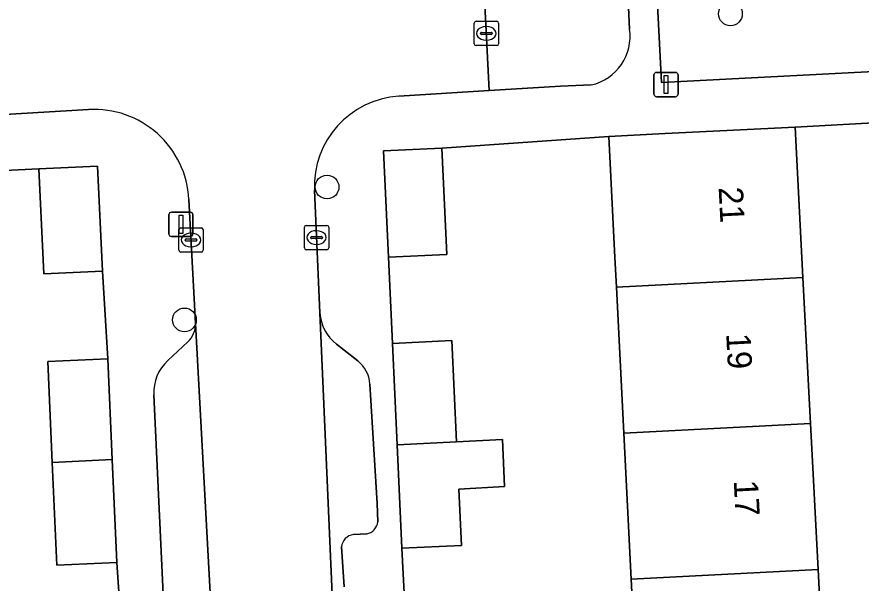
# Model space of a CAD drawing. Extents: x 161084 to 161928, y 385354 to 386522.
# Drawn here: x 161389.16 to 161423.93, y 385507.46 to 385530.8 of the extents above; entities that cross this region are included whole.
import ezdxf

# ---------------------------------------------------------------- set-up
doc = ezdxf.new("R2010")
doc.units = 0
for name, color, linetype in [('IMGEO_Boom', 7, 'Continuous'), ('IMGEO_Erf', 7, 'Continuous'), ('IMGEO_Groenvoorziening', 7, 'Continuous'), ('IMGEO_Kolk', 7, 'Continuous'), ('IMGEO_Lichtmast', 7, 'Continuous'), ('IMGEO_Muur', 7, 'Continuous'), ('IMGEO_Pand', 7, 'Continuous'), ('IMGEO_Pand_nummerreeks', 7, 'Continuous'), ('IMGEO_Parkeervlak_open', 7, 'Continuous'), ('IMGEO_Rijbaan_lokaal_open', 7, 'Continuous'), ('IMGEO_Voetpad_open', 7, 'Continuous')]:
    doc.layers.add(name, color=color, linetype=linetype)

msp = doc.modelspace()

# ---------------------------------------------------------------- linework, layer by layer
at = {"layer": 'IMGEO_Boom'}
for centre in [(161418.548, 385530.919), (161401.934, 385523.786), (161396.06, 385518.31)]:
    msp.add_circle(centre, 0.489, dxfattribs=at)
at = {"layer": 'IMGEO_Erf'}
for points in [[(161425.182, 385526.476), (161421.216, 385526.254), (161421.535, 385520.062), (161421.846, 385514.041), (161422.156, 385508.02), (161422.467, 385501.999), (161422.57, 385500), (161422.777, 385495.978), (161423.088, 385489.958), (161423.399, 385483.937), (161423.709, 385477.916), (161424.02, 385471.895), (161424.33, 385465.874), (161424.65, 385459.679), (161419.05, 385459.388), (161419.359, 385453.441), (161419.358, 385452.841), (161429.459, 385453.441)], [(161414.767, 385501.601), (161414.461, 385507.622), (161414.155, 385513.644), (161413.849, 385519.665), (161413.788, 385520.876), (161413.546, 385525.87), (161406.663, 385525.382), (161406.863, 385521.006), (161404.459, 385520.896), (161404.626, 385517.344), (161407.077, 385517.457), (161407.269, 385513.289), (161409.159, 385513.386), (161409.249, 385511.439), (161407.358, 385511.341), (161407.465, 385509.014), (161405.014, 385508.902), (161405.206, 385505.204)], [(161394.687, 385480.676), (161394.502, 385484.379), (161392.074, 385484.26), (161391.874, 385488.326), (161391.66, 385492.693), (161394.088, 385492.812), (161393.902, 385496.387), (161391.492, 385496.269), (161391.304, 385500), (161391.285, 385500.382), (161391.073, 385504.601), (161393.525, 385504.669), (161393.274, 385508.311), (161390.803, 385508.201), (161390.615, 385512.436), (161390.43, 385516.594), (161392.9, 385516.704), (161392.682, 385520.324), (161390.265, 385520.214), (161390.069, 385524.53), (161383.553, 385524.217)]]:
    msp.add_lwpolyline(points, dxfattribs=at)
at = {"layer": 'IMGEO_Groenvoorziening'}
msp.add_lwpolyline([(161423.5, 385567.403), (161417.869, 385567.12), (161418.115, 385562.333), (161418.509, 385554.67), (161418.697, 385551.01), (161419.118, 385544.317), (161419.162, 385543.217), (161419.276, 385541.405), (161417.489, 385541.292), (161417.374, 385543.105), (161414.936, 385543.029), (161415.708, 385528.098), (161424.995, 385528.578)], dxfattribs=at)
at = {"layer": 'IMGEO_Kolk'}
for p, q in [((161407.996, 385529.69), (161407.996, 385530.542)), ((161408.071, 385530.616), (161408.923, 385530.616)), ((161408.484, 385530.396), (161408.509, 385530.396)), ((161408.997, 385530.542), (161408.997, 385529.69)), ((161408.255, 385530.11), (161408.255, 385530.122)), ((161408.693, 385530.073), (161408.295, 385530.073)), ((161408.298, 385530.159), (161408.696, 385530.159)), ((161408.739, 385530.122), (161408.739, 385530.11)), ((161408.507, 385529.836), (161408.482, 385529.836)), ((161408.923, 385529.616), (161408.071, 385529.616)), ((161395.832, 385521.179), (161395.832, 385522.031)), ((161395.907, 385522.105), (161396.759, 385522.105)), ((161396.833, 385522.031), (161396.833, 385521.179)), ((161401.001, 385521.278), (161401.001, 385522.13)), ((161401.076, 385522.204), (161401.928, 385522.204)), ((161402.002, 385522.13), (161402.002, 385521.278)), ((161396.32, 385521.885), (161396.345, 385521.885)), ((161401.26, 385521.698), (161401.26, 385521.71)), ((161401.303, 385521.747), (161401.701, 385521.747)), ((161401.489, 385521.984), (161401.514, 385521.984)), ((161401.744, 385521.71), (161401.744, 385521.698)), ((161396.091, 385521.599), (161396.091, 385521.611)), ((161396.529, 385521.562), (161396.131, 385521.562)), ((161396.134, 385521.648), (161396.532, 385521.648)), ((161396.575, 385521.611), (161396.575, 385521.599)), ((161401.698, 385521.661), (161401.3, 385521.661)), ((161401.512, 385521.424), (161401.487, 385521.424)), ((161396.759, 385521.105), (161395.907, 385521.105)), ((161396.343, 385521.325), (161396.318, 385521.325)), ((161401.928, 385521.204), (161401.076, 385521.204))]:
    msp.add_line(p, q, dxfattribs=at)
for points in [[(161407.996, 385529.69), (161407.996, 385530.542)], [(161408.071, 385530.616), (161408.923, 385530.616)], [(161408.997, 385530.542), (161408.997, 385529.69)], [(161408.923, 385529.616), (161408.071, 385529.616)], [(161395.832, 385521.179), (161395.832, 385522.031)], [(161395.907, 385522.105), (161396.759, 385522.105)], [(161396.833, 385522.031), (161396.833, 385521.179)], [(161401.001, 385521.278), (161401.001, 385522.13)], [(161401.076, 385522.204), (161401.928, 385522.204)], [(161402.002, 385522.13), (161402.002, 385521.278)], [(161396.759, 385521.105), (161395.907, 385521.105)], [(161401.928, 385521.204), (161401.076, 385521.204)]]:
    msp.add_lwpolyline(points, dxfattribs=at)
for centre, radius, start, end in [((161408.073, 385530.54), 0.0765, 91.552, 178.448), ((161408.073, 385530.54), 0.0765, 91.552, 178.448), ((161408.921, 385530.54), 0.0765, 1.552, 88.448), ((161408.921, 385530.54), 0.0765, 1.552, 88.448), ((161408.295, 385530.119), 0.0403, 85.8775, 175.7526), ((161408.292, 385530.109), 0.0366, 178.938, 274.7102), ((161408.696, 385530.116), 0.043, 264.8664, 352.4533), ((161408.7, 385530.121), 0.0386, 1.7309, 96.639), ((161408.073, 385529.692), 0.0765, 181.552, 268.448), ((161408.073, 385529.692), 0.0765, 181.552, 268.448), ((161408.921, 385529.692), 0.0765, 271.552, 358.448), ((161408.921, 385529.692), 0.0765, 271.552, 358.448), ((161395.909, 385522.029), 0.0765, 91.552, 178.448), ((161395.909, 385522.029), 0.0765, 91.552, 178.448), ((161396.757, 385522.029), 0.0765, 1.552, 88.448), ((161396.757, 385522.029), 0.0765, 1.552, 88.448), ((161401.078, 385522.128), 0.0765, 91.552, 178.448), ((161401.078, 385522.128), 0.0765, 91.552, 178.448), ((161401.926, 385522.128), 0.0765, 1.552, 88.448), ((161401.926, 385522.128), 0.0765, 1.552, 88.448), ((161401.3, 385521.707), 0.0403, 85.8775, 175.7526), ((161401.297, 385521.697), 0.0366, 178.938, 274.7102), ((161401.701, 385521.704), 0.043, 264.8664, 352.4533), ((161401.705, 385521.709), 0.0386, 1.7309, 96.639), ((161396.131, 385521.608), 0.0403, 85.8775, 175.7526), ((161396.128, 385521.598), 0.0366, 178.938, 274.7102), ((161396.532, 385521.605), 0.043, 264.8664, 352.4533), ((161396.536, 385521.61), 0.0386, 1.7309, 96.639), ((161395.909, 385521.181), 0.0765, 181.552, 268.448), ((161395.909, 385521.181), 0.0765, 181.552, 268.448), ((161396.757, 385521.181), 0.0765, 271.552, 358.448), ((161396.757, 385521.181), 0.0765, 271.552, 358.448), ((161401.078, 385521.28), 0.0765, 181.552, 268.448), ((161401.078, 385521.28), 0.0765, 181.552, 268.448), ((161401.926, 385521.28), 0.0765, 271.552, 358.448), ((161401.926, 385521.28), 0.0765, 271.552, 358.448)]:
    msp.add_arc(centre, radius, start, end, dxfattribs=at)
for centre, major_axis, ratio, start_param, end_param in [((161408.483, 385530.116), (-0.387, 0.002), 0.722429, 4.712389, 7.853982), ((161408.508, 385530.116), (-0.39, 0.002), 0.717154, 1.570796, 4.712389), ((161396.319, 385521.605), (-0.387, 0.002), 0.722429, 4.712389, 7.853982), ((161396.344, 385521.605), (-0.39, 0.002), 0.717154, 1.570796, 4.712389), ((161401.488, 385521.704), (-0.387, 0.002), 0.722429, 4.712389, 7.853982), ((161401.513, 385521.704), (-0.39, 0.002), 0.717154, 1.570796, 4.712389)]:
    msp.add_ellipse(centre, major_axis=major_axis, ratio=ratio, start_param=start_param, end_param=end_param, dxfattribs=at)
at = {"layer": 'IMGEO_Lichtmast'}
for p, q in [((161415.398, 385527.609), (161415.398, 385528.409)), ((161415.398, 385528.409), (161415.398, 385527.609)), ((161415.498, 385528.509), (161416.288, 385528.509)), ((161416.288, 385528.509), (161415.498, 385528.509)), ((161416.388, 385528.409), (161416.388, 385527.609)), ((161416.388, 385527.609), (161416.388, 385528.409)), ((161416.288, 385527.509), (161415.498, 385527.509)), ((161415.498, 385527.509), (161416.288, 385527.509)), ((161395.523, 385522.749), (161396.313, 385522.749)), ((161396.313, 385522.749), (161395.523, 385522.749)), ((161395.423, 385521.849), (161395.423, 385522.649)), ((161395.423, 385522.649), (161395.423, 385521.849)), ((161396.413, 385522.649), (161396.413, 385521.849)), ((161396.413, 385521.849), (161396.413, 385522.649)), ((161396.313, 385521.749), (161395.523, 385521.749)), ((161395.523, 385521.749), (161396.313, 385521.749))]:
    msp.add_line(p, q, dxfattribs=at)
for points in [[(161415.818, 385528.384), (161415.968, 385528.384), (161415.968, 385527.634), (161415.818, 385527.634), (161415.818, 385528.384)], [(161395.843, 385522.624), (161395.993, 385522.624), (161395.993, 385521.874), (161395.843, 385521.874), (161395.843, 385522.624)]]:
    msp.add_lwpolyline(points, dxfattribs=at)
for centre, start, end in [((161415.498, 385528.409), 90, 180), ((161415.498, 385528.409), 90, 180), ((161416.288, 385528.409), 0, 90), ((161416.288, 385528.409), 360, 90), ((161415.498, 385527.609), 180, 270), ((161415.498, 385527.609), 180, 270), ((161416.288, 385527.609), 270, 0), ((161416.288, 385527.609), 270, 0), ((161395.523, 385522.649), 90, 180), ((161395.523, 385522.649), 90, 180), ((161396.313, 385522.649), 0, 90), ((161396.313, 385522.649), 360, 90), ((161395.523, 385521.849), 180, 270), ((161395.523, 385521.849), 180, 270), ((161396.313, 385521.849), 270, 0), ((161396.313, 385521.849), 270, 0)]:
    msp.add_arc(centre, 0.1, start, end, dxfattribs=at)
at = {"layer": 'IMGEO_Muur'}
for points in [[(161406.663, 385525.382), (161413.546, 385525.87)], [(161383.553, 385524.217), (161390.069, 385524.53)]]:
    msp.add_lwpolyline(points, dxfattribs=at)
at = {"layer": 'IMGEO_Pand'}
for points in [[(161415.853, 385525.986), (161413.546, 385525.87), (161413.788, 385520.876), (161413.849, 385519.665), (161421.535, 385520.062), (161421.216, 385526.254)], [(161404.259, 385525.272), (161404.459, 385520.896), (161406.863, 385521.006), (161406.663, 385525.382)], [(161392.486, 385524.64), (161390.069, 385524.53), (161390.265, 385520.214), (161392.682, 385520.324)], [(161413.849, 385519.665), (161414.155, 385513.644), (161421.846, 385514.041), (161421.535, 385520.062)], [(161407.077, 385517.457), (161404.626, 385517.344), (161404.818, 385513.162), (161407.269, 385513.289)], [(161392.9, 385516.704), (161390.43, 385516.594), (161390.615, 385512.436), (161393.084, 385512.565)], [(161414.155, 385513.644), (161414.461, 385507.622), (161422.156, 385508.02), (161421.846, 385514.041)], [(161407.358, 385511.341), (161409.249, 385511.439), (161409.159, 385513.386), (161407.269, 385513.289), (161404.818, 385513.162), (161405.014, 385508.902), (161407.465, 385509.014)], [(161393.084, 385512.565), (161390.615, 385512.436), (161390.803, 385508.201), (161393.274, 385508.311)], [(161414.461, 385507.622), (161414.767, 385501.601), (161422.467, 385501.999), (161422.156, 385508.02)]]:
    msp.add_lwpolyline(points, close=True, dxfattribs=at)
at = {"layer": 'IMGEO_Parkeervlak_open'}
for points in [[(161411.888, 385542.818), (161410.646, 385542.824), (161407.857, 385542.687), (161408.615, 385527.761), (161411.545, 385527.946), (161412.816, 385527.991)], [(161414.395, 385530.296), (161413.899, 385541.111)], [(161401.636, 385518.603), (161402.21, 385505.43), (161402.592, 385500), (161404.623, 385460.419)], [(161399.561, 385459.962), (161397.507, 385500), (161396.523, 385518.161)], [(161396.198, 385517.403), (161395.372, 385516.635)], [(161403.198, 385516.627), (161402.327, 385517.305)], [(161404.026, 385509.99), (161403.993, 385510.739), (161403.698, 385515.668)], [(161394.8, 385515.226), (161395.52, 385499.972), (161395.632, 385497.526)], [(161403.021, 385509.463), (161403.568, 385509.492)], [(161402.646, 385507.306), (161402.532, 385508.956)]]:
    msp.add_lwpolyline(points, dxfattribs=at)
for centre, radius, start, end in [((161412.356, 385529.999), 2.06, 282.8919, 8.2833), ((161403.432, 385518.726), 1.8, 183.9171, 232.1408), ((161395.506, 385518.148), 1.017, 312.8633, 0.7213), ((161396.598, 385515.317), 1.8, 132.9241, 182.8854), ((161402.396, 385515.599), 1.304, 3.0356, 52.0374), ((161403.456, 385510.055), 0.574, 281.2514, 353.5404), ((161403.084, 385508.913), 0.553, 96.4918, 175.579)]:
    msp.add_arc(centre, radius, start, end, dxfattribs=at)
at = {"layer": 'IMGEO_Rijbaan_lokaal_open'}
for points in [[(161408.615, 385527.761), (161407.857, 385542.687)], [(161404.897, 385527.528), (161408.615, 385527.761)], [(161388.666, 385526.781), (161392.115, 385526.978)], [(161401.636, 385518.603), (161401.416, 385523.656)], [(161396.246, 385523.278), (161396.523, 385518.161)], [(161404.623, 385460.419), (161402.592, 385500), (161402.21, 385505.43), (161401.636, 385518.603)], [(161396.523, 385518.161), (161397.507, 385500), (161399.561, 385459.962)]]:
    msp.add_lwpolyline(points, dxfattribs=at)
for centre, radius, start, end in [((161405.131, 385523.817), 3.719, 93.6137, 182.4741), ((161392.338, 385523.071), 3.914, 3.0342, 93.2663)]:
    msp.add_arc(centre, radius, start, end, dxfattribs=at)
at = {"layer": 'IMGEO_Voetpad_open'}
for points in [[(161424.995, 385528.578), (161415.708, 385528.098), (161414.936, 385543.029), (161417.374, 385543.105), (161419.162, 385543.217), (161419.118, 385544.317), (161417.121, 385544.182), (161412.904, 385544.022), (161408.688, 385543.863), (161405.079, 385543.654), (161400.886, 385543.429), (161396.693, 385543.204), (161396.75, 385542.155), (161407.857, 385542.687), (161410.646, 385542.824), (161411.888, 385542.818)], [(161413.899, 385541.111), (161414.395, 385530.296)], [(161412.816, 385527.991), (161411.545, 385527.946), (161408.615, 385527.761), (161404.897, 385527.528)], [(161392.115, 385526.978), (161388.666, 385526.781), (161384.439, 385526.54)], [(161406.529, 385481.207), (161406.331, 385484.996), (161406.126, 385489.082), (161405.915, 385493.3), (161405.708, 385496.967), (161405.523, 385500), (161405.455, 385501.12), (161405.206, 385505.204), (161405.014, 385508.902), (161404.818, 385513.162), (161404.626, 385517.344), (161404.459, 385520.896), (161404.259, 385525.272), (161406.663, 385525.382), (161413.546, 385525.87), (161415.853, 385525.986), (161421.216, 385526.254), (161425.182, 385526.476)], [(161383.553, 385524.217), (161390.069, 385524.53), (161392.486, 385524.64), (161392.682, 385520.324), (161392.9, 385516.704), (161393.084, 385512.565), (161393.274, 385508.311), (161393.525, 385504.669), (161393.715, 385500.509), (161393.738, 385500), (161393.902, 385496.387), (161394.088, 385492.812), (161394.302, 385488.453), (161394.502, 385484.379), (161394.687, 385480.676)], [(161401.416, 385523.656), (161401.636, 385518.603)], [(161396.523, 385518.161), (161396.246, 385523.278)], [(161395.372, 385516.635), (161396.198, 385517.403)], [(161402.327, 385517.305), (161403.198, 385516.627)], [(161403.698, 385515.668), (161403.993, 385510.739), (161404.026, 385509.99)], [(161395.632, 385497.526), (161395.52, 385499.972), (161394.8, 385515.226)], [(161403.568, 385509.492), (161403.021, 385509.463)], [(161402.532, 385508.956), (161402.646, 385507.306)]]:
    msp.add_lwpolyline(points, dxfattribs=at)
for centre, radius, start, end in [((161412.356, 385529.999), 2.06, 282.8919, 8.2833), ((161405.131, 385523.817), 3.719, 93.6137, 182.4741), ((161392.338, 385523.071), 3.914, 3.0342, 93.2663), ((161403.432, 385518.726), 1.8, 183.9171, 232.1408), ((161395.506, 385518.148), 1.017, 312.8633, 0.7213), ((161396.598, 385515.317), 1.8, 132.9241, 182.8854), ((161402.396, 385515.599), 1.304, 3.0356, 52.0374), ((161403.456, 385510.055), 0.574, 281.2514, 353.5404), ((161403.084, 385508.913), 0.553, 96.4918, 175.579)]:
    msp.add_arc(centre, radius, start, end, dxfattribs=at)

# ---------------------------------------------------------------- texts
at = {"layer": 'IMGEO_Pand_nummerreeks'}
for s, p in [('21', (161418.06, 385523.771)), ('19', (161418.371, 385517.741)), ('17', (161418.683, 385511.689))]:
    msp.add_text(s, height=1, rotation=272.9528, dxfattribs=at).set_placement(p)

doc.saveas('drawing.dxf')
